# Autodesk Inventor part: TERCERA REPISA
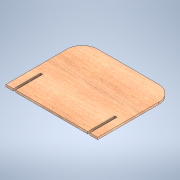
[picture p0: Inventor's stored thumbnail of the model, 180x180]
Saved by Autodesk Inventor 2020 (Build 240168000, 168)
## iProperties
Created: 2020-03
Part Number: TERCERA REPISA
Material: Madera (abedul)
Document SubType Name: Modeling
Designer: Arias
Density: 0.55 g/cm^3
Appearance: Abedul - Natural pulido
Author: Arias
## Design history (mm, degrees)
sketch "Boceto1"
  geometry: L1 (0, 0)-(480, 0); L2 (480, 0)-(480, -320); L3 (400, -400)-(80, -400); L4 (0, -320)-(0, 0); L5 (440, 0)-(440, -141.897); L6 (428.9, 0)-(428.9, -141.897); L7 (51.1, 0)-(51.1, -141.897); L8 (40, 0)-(40, -141.897); L9 (428.9, -141.897)-(440, -141.897); L10 (40, -141.897)-(51.1, -141.897); A1 r 80 centre (400, -320) between (400, -400) and (480, -320); A2 r 80 centre (80, -320) between (0, -320) and (80, -400); 2 further points
  constraints: 20 end point, 8 point on line, 4 point on circle, 4 tangent, 4 vertical, 2 centre point, 2 parallel, 1 horizontal, 1 perpendicular
  dimensions: "d0" = 400 distance of L1.end point (480, -400); "d1" = 480 distance of point (480, -400) point (0, -400); "d2" = 141.897 distance of L8.start L8.end; "d3" = 141.897 distance of L7.start L7.end; "d4" = 141.897 distance of L6.start L6.end; "d5" = 141.897 distance of L5.start L5.end; "d6" = 11.1 distance between parallel lines of L5 L6; "d7" = 11.1 distance between parallel lines of L7 L8; "d8" = 400 distance between parallel lines of L8 L5; "d9" = 40 distance between parallel lines of L4 L8; "d12" = 80 radius of A1; "d13" = 80 radius of A2 (derived)
extrude "Extrusión1" new body sketch "Boceto1" distance "d10" = 11.1; taper "d11" = 0 deg
node "Sólido1"
